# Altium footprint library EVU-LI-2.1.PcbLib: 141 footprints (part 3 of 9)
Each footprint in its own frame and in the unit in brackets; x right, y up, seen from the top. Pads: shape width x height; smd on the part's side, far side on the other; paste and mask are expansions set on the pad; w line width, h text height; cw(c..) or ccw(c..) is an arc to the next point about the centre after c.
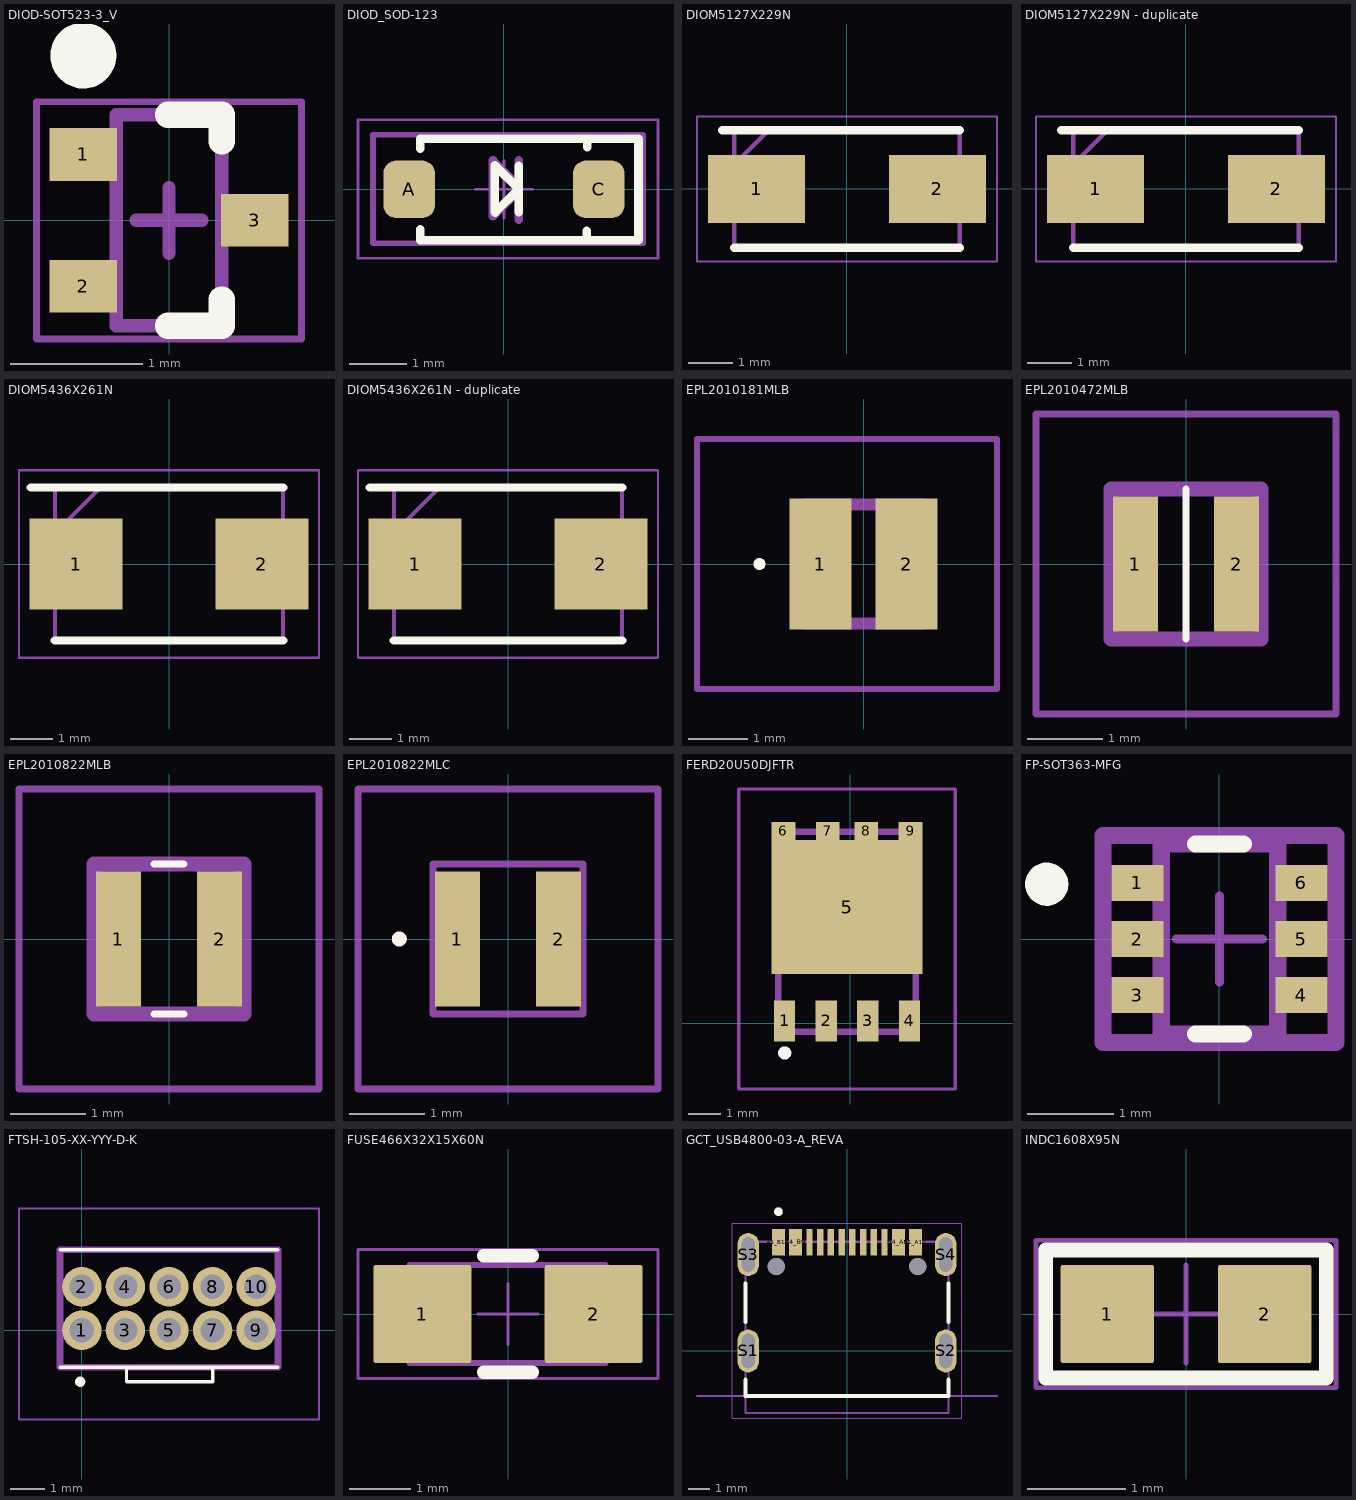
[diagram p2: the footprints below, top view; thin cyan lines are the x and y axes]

## DIOD-SOT523-3_V [mm] "SOT523, 3-Leads, Body 1.6x0.8mm, Pitch 0.50mm"
height 0.862
pads (3):
  rect 0.51x0.4 smd: 1(-0.65,0.5) 2(-0.65,-0.5) 3(0.65,0)
Top Overlay:
  circle w0.25: c-0.65,1.25 r0.125
  lines w0.2: -0.008,-0.8 0.4,-0.8 0.4,-0.6 ; -0.008,0.8 0.4,0.8 0.4,0.6
Mechanical 13:
  lines w0.1: -0.4,-0.8 -0.4,0.8 0.4,0.8 0.4,-0.8 -0.4,-0.8
Top Courtyard:
  lines w0.05: -1.005,-0.9 -1.005,0.9 1.005,0.9 1.005,-0.9 -1.005,-0.9
  lines w0.1: -0.25,0 0.25,0 ; 0,-0.25 0,0.25
3D body: height 0.86, standoff 0, extent -0.4,-0.8 0.4,0.8

## DIOD_SOD-123 [mm]
height 1.2
pads (2):
  rrect50% 0.9x1 smd: A(-1.65,0) C(1.65,0)
Top Overlay:
  lines w0.15: -1.46,-0.7 -1.46,-0.89 2.34,-0.89 2.34,0.73 ; -1.46,0.71 -1.46,0.88 1.93,0.88 ; 0.26,-0.4 0.26,0 -0.16,0.42 -0.16,-0.4 -0.155,-0.405 0.26,0.01 0.26,0.405 ; 1.44,-0.89 1.44,-0.72 ; 1.45,0.73 1.45,0.88 2.34,0.88 2.34,0.71
Top Assembly:
  lines w0.1: -2.28,-0.94 2.42,-0.94 2.42,0.95 -2.28,0.95 -2.28,-0.94
  lines w0.15: 0.26,-0.53 0.26,0.05 -0.19,0.5 -0.19,-0.47 0.26,-0.02 0.26,0.5
  text ".Designator" at -2.241,0.568 h0.7
Top Value:
  text ".Comment" at -2.28,-0.726 h0.7
Top Courtyard:
  lines w0.05: -0.5,0 0.5,0 ; 0,-0.5 0,0.5 ; -2.54,-1.2 2.68,-1.2 2.68,1.21 -2.54,1.21 -2.54,-1.2
3D body "SOD123.step": height 1.27, standoff 0, extent -1.85,-0.8 1.85,0.8

## DIOM5127X229N [mm]
pads (2):
  rect 2.2x1.55 smd: 1(-2.05,0) 2(2.05,0)
Top Overlay:
  lines w0.2: -2.825,1.332 2.552,1.332 ; -2.552,-1.332 2.552,-1.332
Mechanical 13:
  lines w0.1: -2.552,0.558 -1.778,1.332 ; -2.552,-1.332 2.552,-1.332 2.552,1.332 -2.552,1.332 -2.552,-1.332
Top Courtyard:
  lines w0.05: -3.4,-1.645 3.4,-1.645 3.4,1.645 -3.4,1.645 -3.4,-1.645
3D body "ES1B-E3_61T.stp": height 2.29, standoff 0, extent -2.552,-1.332 2.552,1.332

## DIOM5127X229N - duplicate [mm]
pads (2):
  rect 2.2x1.55 smd: 1(-2.05,0) 2(2.05,0)
Top Overlay:
  lines w0.2: -2.825,1.332 2.552,1.332 ; -2.552,-1.332 2.552,-1.332
Mechanical 13:
  lines w0.1: -2.552,0.558 -1.778,1.332 ; -2.552,-1.332 2.552,-1.332 2.552,1.332 -2.552,1.332 -2.552,-1.332
Top Courtyard:
  lines w0.05: -3.4,-1.645 3.4,-1.645 3.4,1.645 -3.4,1.645 -3.4,-1.645
3D body "ES1B-E3_61T.stp": height 2.29, standoff 0, extent -2.552,-1.332 2.552,1.332

## DIOM5436X261N [mm]
pads (2):
  rect 2.2x2.15 smd: 1(-2.2,0) 2(2.2,0)
Top Overlay:
  lines w0.2: -3.275,1.81 2.7,1.81 ; -2.7,-1.81 2.7,-1.81
Mechanical 13:
  lines w0.1: -2.7,0.735 -1.625,1.81 ; -2.7,-1.81 2.7,-1.81 2.7,1.81 -2.7,1.81 -2.7,-1.81
Top Courtyard:
  lines w0.05: -3.55,-2.22 3.55,-2.22 3.55,2.22 -3.55,2.22 -3.55,-2.22
3D body "SMBJ51A.stp": height 2.61, standoff 0, extent -2.7,-1.81 2.7,1.81

## DIOM5436X261N - duplicate [mm]
pads (2):
  rect 2.2x2.15 smd: 1(-2.2,0) 2(2.2,0)
Top Overlay:
  lines w0.2: -3.275,1.81 2.7,1.81 ; -2.7,-1.81 2.7,-1.81
Mechanical 13:
  lines w0.1: -2.7,0.735 -1.625,1.81 ; -2.7,-1.81 2.7,-1.81 2.7,1.81 -2.7,1.81 -2.7,-1.81
Top Courtyard:
  lines w0.05: -3.55,-2.22 3.55,-2.22 3.55,2.22 -3.55,2.22 -3.55,-2.22
3D body "SMBJ51A.stp": height 2.61, standoff 0, extent -2.7,-1.81 2.7,1.81

## EPL2010181MLB [mm]
pads (2):
  rect 1.04x2.2 smd: 1(-0.725,0) 2(0.725,0)
Top Overlay:
  lines w0.1: -1.8,0 ccw(c-1.75,0) -1.7,0 ccw(c-1.75,0) -1.8,0
Mechanical 13:
  lines w0.2: -1,-1 1,-1 1,1 -1,1 -1,-1
Top Courtyard:
  lines w0.1: -2.8,-2.1 2.245,-2.1 2.245,2.1 -2.8,2.1 -2.8,-2.1

## EPL2010472MLB [mm]
pads (2):
  rect 0.6x1.8 smd: 1(-0.675,0) 2(0.675,0)
Top Overlay:
  lines w0.1: 0,-1 0,1
Mechanical 13:
  lines w0.2: -1,-1 -1,1 1,1 1,-1 -1,-1
Top Courtyard:
  lines w0.1: -2,-2 -2,2 2,2 2,-2 -2,-2
3D body "EPL2010-472MLB.stp": height 1.15, standoff 0, extent -1,-1 1,1

## EPL2010822MLB [mm]
pads (2):
  rect 0.6x1.8 smd: 1(-0.675,0) 2(0.675,0)
Top Overlay:
  lines w0.1: -0.2,-1 0.2,-1 ; -0.2,1 0.2,1
Mechanical 13:
  lines w0.2: -1,-1 1,-1 1,1 -1,1 -1,-1
Top Courtyard:
  lines w0.1: -2,-2 2,-2 2,2 -2,2 -2,-2
3D body "EPL2010-822MLB.stp": height 1.15, standoff 0, extent -1,-1 1,1

## EPL2010822MLC [mm]
pads (2):
  rect 0.6x1.8 smd: 1(-0.675,0) 2(0.675,0)
Top Overlay:
  lines w0.1: -1.5,0 ccw(c-1.45,0) -1.4,0 ccw(c-1.45,0) -1.5,0
Mechanical 13:
  lines w0.1: -1,-1 -1,1 1,1 1,-1 -1,-1
Top Courtyard:
  lines w0.1: -2,-2 -2,2 2,2 2,-2 -2,-2
3D body "EPL2010-822MLC.stp": height 1.15, standoff 0, extent -1,-1 1,1

## FERD20U50DJFTR [mm]
pads (9):
  rect 0.65x1.25 smd: 1(-2.005,0.075) 2(-0.735,0.075) 3(0.535,0.075) 4(1.805,0.075)
  rect 4.6x4.1 smd: 5(-0.1,3.55)
  rect 0.725x0.55 smd: 6(-2.038,5.875) 7(-0.688,5.875) 8(0.487,5.875) 9(1.837,5.875)
Top Overlay:
  lines w0.2: -2.1,-0.9 ccw(c-2,-0.9) -1.9,-0.9 ccw(c-2,-0.9) -2.1,-0.9
Mechanical 13:
  lines w0.2: -2.2,-0.25 -2.2,5.85 2,5.85 2,-0.25 -2.2,-0.25
Top Courtyard:
  lines w0.1: -3.4,-2 -3.4,7.15 3.2,7.15 3.2,-2 -3.4,-2
3D body "STL220N6F7.stp": height 1, standoff 0, extent -2.69,-0.285 2.51,5.865

## FP-SOT363-MFG [mm]
pads (6):
  rect 0.6x0.42 smd paste+0 mask+0: 1(-0.95,0.65) 2(-0.95,0) 3(-0.95,-0.65) 4(0.95,-0.65) 5(0.95,0) 6(0.95,0.65)
Top Overlay:
  circle w0.25: c-2,0.635 r0.125
  lines w0.2: -0.275,-1.1 0.275,-1.1 ; -0.275,1.1 0.275,1.1
Top Assembly:
  lines w0.2: -1.35,-1.2 -1.35,1.2 1.35,1.2 1.35,-1.2 -1.35,-1.2
  text ".Designator" at 0,0.188 h1
Top 3D Body:
  lines w0.2: -0.675,-1.1 -0.675,1.1 0.675,1.1 0.675,-1.1 -0.675,-1.1
Top Component Center:
  lines w0.1: -0.5,0 0.5,0 ; 0,-0.5 0,0.5
Top Courtyard:
  lines w0.2: -1.35,-1.2 -1.35,1.2 1.35,1.2 1.35,-1.2 -1.35,-1.2
3D body "Trans_Diodes_BSS8402DW-7-F_eec.STEP": height 0.25, standoff 0, extent -1.35,-1.2 1.35,1.2

## FTSH-105-XX-YYY-D-K [mm]
pads (10):
  round 1.15 hole 0.71: 1(0,0) 2(0,1.27) 3(1.27,0) 4(1.27,1.27) 5(2.54,0) 6(2.54,1.27) 7(3.81,0) 8(3.81,1.27) 9(5.08,0) 10(5.08,1.27)
Top Overlay:
  circle w0.2: c-0.05,-1.5 r0.05
  lines w0.1: -0.635,-1.08 5.715,-1.08 ; -0.635,2.35 5.715,2.35 ; 1.3,-1.5 3.81,-1.5 3.81,-1.1 1.3,-1.1 1.3,-1.5
Mechanical 13:
  lines w0.2: -0.635,-1.08 5.715,-1.08 5.715,2.35 -0.635,2.35 -0.635,-1.08
Top Courtyard:
  lines w0.05: -1.835,-2.6 6.915,-2.6 6.915,3.55 -1.835,3.55 -1.835,-2.6
3D body "FTSH-105-01-F-D-K.stp": height 5.94, standoff -1.92, extent -0.635,-1.245 5.715,2.185

## FUSE466X32X15X60N [mm]
pads (2):
  rrect5% 1.6x1.6 smd mask+0.05: 1(-1.4,0) 2(1.4,0)
Top Overlay:
  lines w0.22: -0.4,-0.95 0.4,-0.95 ; -0.4,0.95 0.4,0.95
Top Assembly:
  lines w0.1: -1.205,-0.799 -1.205,0.801 ; 1.195,-0.799 1.195,0.801 ; -1.605,-0.799 1.595,-0.799 1.595,0.801 -1.605,0.801 -1.605,-0.799
Top Designator:
  text ".Designator" at -3.25,-0.3 h1.5
Mechanical 9:
  text ".MARK" at -1.575,-0.35 h1.2
Top Courtyard:
  lines w0.05: -0.5,0 0.5,0 ; 0,-0.5 0,0.5 ; -2.45,-1.05 2.45,-1.05 2.45,1.05 -2.45,1.05 -2.45,-1.05
3D body "FUSE466.STEP": height 0.66, standoff 0, extent -1.65,-0.8 1.65,0.8

## GCT_USB4800-03-A_REVA [mm]
height 5.38
pads (18):
  rect 0.6x1.25 smd: A1_B12(-3.2,5.075) A4_B9(-2.4,5.075) B1_A12(3.2,5.075) B4_A9(2.4,5.075)
  rect 0.3x1.25 smd: A5(-1.25,5.075) A6(-0.25,5.075) A7(0.25,5.075) A8(1.25,5.075) B5(1.75,5.075) B6(0.75,5.075) B7(-0.75,5.075) B8(-1.75,5.075)
  oval 1x2 hole 0.6 slot 1.6 at 90 deg: S1(-4.61,0) S2(4.61,0) S3(-4.61,4.5) S4(4.61,4.5)
  round 0.8 hole 0.8 unplated: ""(-3.3,3.94) ""(3.3,3.94)
Top Overlay:
  circle w0.2: c-3.2,6.5 r0.1
  lines w0.2: -4.735,-1.35 -4.735,-2.1 4.735,-2.1 4.735,-1.35 ; -4.735,1.35 -4.735,3.15 ; 4.735,1.35 4.735,3.15
Mechanical 13:
  circle w0.2: c-3.2,6.5 r0.1
  lines w0.1: -7,-2.1 -4.735,-2.1 ; 7,-2.1 4.735,-2.1 ; -4.735,-2.1 4.735,-2.1 ; -4.735,-2.1 -4.735,5.1 4.735,5.1 4.735,-2.1 ; -4.735,-2.1 -4.735,-2.9 4.735,-2.9 4.735,-2.1
  text "PCB EDGE" at 5.5,-1.9 h0.81
Top Courtyard:
  lines w0.05: -5.36,-3.15 -5.36,5.95 5.36,5.95 5.36,-3.15 -5.36,-3.15
3D body "step_temp.STEP": height 5.38, standoff -1.3, extent -4.735,-2.9 4.735,5.5

## INDC1608X95N [mm]
pads (2):
  rrect5% 0.95x1 smd mask+0.07: 1(-0.8,0) 2(0.8,0)
Top Overlay:
  lines w0.15: -1.425,-0.65 1.425,-0.65 1.425,0.65 -1.425,0.65 -1.425,-0.65
Top Assembly:
  lines w0.1: -1.45,-0.65 1.45,-0.65 1.45,0.65 -1.45,0.65 -1.45,-0.65
Top Designator:
  text ".Designator" at -3.25,-0.3 h1.5
Top Courtyard:
  lines w0.05: -0.5,0 0.5,0 ; 0,-0.5 0,0.5 ; -1.525,-0.75 1.525,-0.75 1.525,0.75 -1.525,0.75 -1.525,-0.75
3D body "BLM18__TN1.STEP": height 0.65, standoff 0, extent -0.875,-0.475 0.875,0.475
